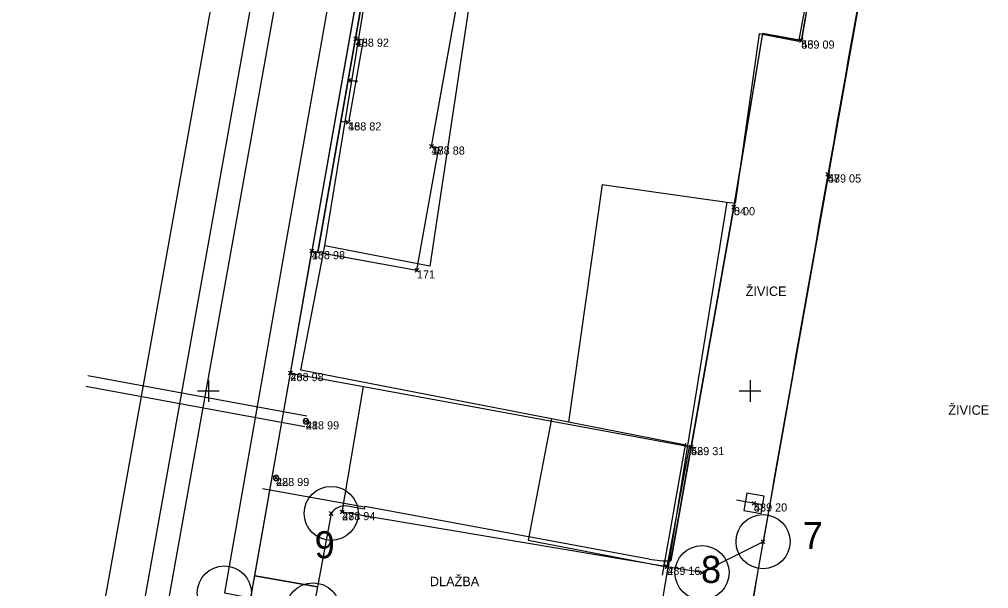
# Model space of a CAD drawing. Extents: x -866624 to -866276, y -1050208 to -1049940.
# Drawn here: x -866486.98 to -866451.2, y -1050047.29 to -1050026.29 of the extents above; entities that cross this region are included whole.
import ezdxf

# ---------------------------------------------------------------- set-up
doc = ezdxf.new("R2010")
doc.units = 0
for name, color, linetype in [('00_BODY VYTYČ', 7, 'Continuous'), ('00_POMOCNÉ KCE', 7, 'Continuous'), ('09_PODLAHY', 7, 'Continuous'), ('bod-cislo', 7, 'Continuous'), ('bod-oznac', 7, 'Continuous'), ('bod-vyska', 7, 'Continuous'), ('BUDOVY', 7, 'Continuous'), ('CTV-SIT', 7, 'Continuous'), ('Default', 7, 'Continuous'), ('EL-ZAR', 7, 'Continuous'), ('HRAN-LIN', 7, 'Continuous'), ('Hranice', 7, 'Continuous'), ('Hranice další', 7, 'Continuous'), ('Hranice-budov', 7, 'Continuous'), ('KOLEJ', 7, 'Continuous'), ('POTR-ZAR', 7, 'Continuous'), ('TEXT', 7, 'Continuous')]:
    doc.layers.add(name, color=color, linetype=linetype)

# ---------------------------------------------------------------- blocks, each defined once
blk = doc.blocks.new('POINT_DISPLAY')
at = {"layer": 'Default'}
for p, q in [((-0.071, 0.071), (0.071, -0.071)), ((0.071, 0.071), (-0.071, -0.071))]:
    blk.add_line(p, q, dxfattribs=at)
blk = doc.blocks.new('CTVSIT')
at = {"layer": 'Default'}
for p, q in [((0, 2), (0, -2)), ((-2, 0), (2, 0))]:
    blk.add_line(p, q, dxfattribs=at)
blk = doc.blocks.new('200SAH')
at = {"layer": 'POTR-ZAR'}
for p, q in [((0, -0.325), (0, 0.65)), ((0.325, 0.325), (-0.325, 0.325)), ((-0.325, 0.325), (-0.325, -0.325)), ((0.325, -0.325), (0.325, 0.325)), ((-0.325, -0.325), (0.325, -0.325))]:
    blk.add_line(p, q, dxfattribs=at)
blk = doc.blocks.new('vytyčení')
at = {"layer": '00_POMOCNÉ KCE'}
for centre in [(-866034.112, -1050068.345), (-866032.646, -1050070.404), (-866032.762, -1050084.264), (-866029.142, -1050084.394), (-866029.271, -1050087.726)]:
    blk.add_circle(centre, 0.998, dxfattribs=at)
for centre, radius, start, end in [((-865794.817, -1039948.575), 10122.593, 268.4556412, 268.567516), ((-865314.028, -1020722.218), 29354.96, 268.567516, 268.6067194)]:
    blk.add_arc(centre, radius, start, end, dxfattribs=at)
at = {"layer": '09_PODLAHY'}
for points in [[(-866081.414, -1050069.09), (-866081.361, -1050067.121), (-866034.112, -1050068.345), (-866032.646, -1050070.404), (-866032.668, -1050071.704), (-866032.671, -1050071.836), (-866032.872, -1050071.831), (-866032.905, -1050071.604), (-866037.17, -1050071.494), (-866046.156, -1050071.254), (-866052.647, -1050071.161), (-866052.609, -1050069.711), (-866064.905, -1050069.395), (-866064.942, -1050070.845), (-866070.764, -1050070.735), (-866070.738, -1050069.285), (-866080.614, -1050069.109), (-866081.414, -1050069.09)], [(-866037.659, -1050086.526), (-866037.57, -1050083.788), (-866037.437, -1050079.693), (-866037.181, -1050071.494), (-866032.905, -1050071.604)], [(-866037.285, -1050071.717), (-866032.335, -1050071.845)], [(-866032.847, -1050072.408), (-866033.195, -1050083.08), (-866033.095, -1050083.083), (-866033.115, -1050083.714)], [(-866033.176, -1050083.08), (-866033.275, -1050086.913)], [(-866032.762, -1050084.264), (-866030.008, -1050084.365), (-866030.067, -1050086.709), (-866037.659, -1050086.526)], [(-866037.659, -1050086.526), (-866042.227, -1050086.418), (-866042.221, -1050086.198), (-866057.536, -1050085.815), (-866068.352, -1050085.544), (-866071.502, -1050085.465), (-866076.384, -1050085.343), (-866076.386, -1050085.562), (-866042.227, -1050086.418)]]:
    blk.add_lwpolyline(points, dxfattribs=at)
for points in [[(-866042.22, -1050086.198), (-866042.104, -1050082.475), (-866046.696, -1050082.351), (-866046.704, -1050082.624), (-866057.447, -1050082.335), (-866057.533, -1050085.497), (-866057.536, -1050085.815), (-866042.22, -1050086.198)], [(-866030.068, -1050086.709), (-866030.008, -1050084.365), (-866029.142, -1050084.394), (-866029.234, -1050086.729), (-866030.068, -1050086.709)], [(-866076.389, -1050085.553), (-866077.898, -1050085.519), (-866077.927, -1050086.627), (-866076.412, -1050086.552), (-866042.25, -1050087.417), (-866029.271, -1050087.726), (-866029.245, -1050086.729)]]:
    blk.add_lwpolyline(points, close=True, dxfattribs=at)
for centre, radius, start, end in [((-866036.697, -1050072.283), 3.852, 358.1389, 10.1522), ((-866032.516, -1050083.718), 0.599, 179.6517, 245.7505)]:
    blk.add_arc(centre, radius, start, end, dxfattribs=at)

msp = doc.modelspace()

# ---------------------------------------------------------------- linework, layer by layer
at = {"layer": 'BUDOVY'}
for p, q in [((-866471.76, -1050030.98), (-866467.37, -1050006.42)), ((-866455.96, -1050014.96), (-866458.11, -1050027.07)), ((-866459.538, -1050026.817), (-866460.6, -1050033.22)), ((-866458.11, -1050027.07), (-866459.538, -1050026.817)), ((-866472.3, -1050035.55), (-866471.492, -1050031.028)), ((-866471.76, -1050030.98), (-866471.492, -1050031.028)), ((-866460.6, -1050033.22), (-866462.18, -1050042.07)), ((-866476.97, -1050039.34), (-866476.18, -1050034.84)), ((-866476.18, -1050034.84), (-866472.3, -1050035.55)), ((-866476.97, -1050039.34), (-866474.276, -1050039.837)), ((-866475.06, -1050044.47), (-866474.276, -1050039.837)), ((-866463.06, -1050046.49), (-866462.242, -1050042.059)), ((-866462.242, -1050042.059), (-866462.18, -1050042.07)), ((-866463.06, -1050046.49), (-866475.06, -1050044.47))]:
    msp.add_line(p, q, dxfattribs=at)
at = {"layer": 'EL-ZAR'}
for p, q in [((-866484.449, -1050039.431), (-866476.364, -1050040.923)), ((-866484.52, -1050039.825), (-866476.436, -1050041.317))]:
    msp.add_line(p, q, dxfattribs=at)
for centre, start, end in [((-866476.4, -1050041.12), 0, 180), ((-866476.4, -1050041.12), 180, 0), ((-866477.5, -1050043.21), 0, 180), ((-866477.5, -1050043.21), 180, 0)]:
    msp.add_arc(centre, 0.1, start, end, dxfattribs=at)
at = {"layer": 'HRAN-LIN'}
for p, q in [((-866472.79, -1049999.16), (-866484.714, -1050065.787)), ((-866475.964, -1050034.88), (-866470.013, -1050001.227)), ((-866474.813, -1050030.094), (-866474.275, -1050027.05)), ((-866474.57, -1050026.998), (-866474.275, -1050027.05)), ((-866474.839, -1050028.52), (-866474.7, -1050028.478)), ((-866474.839, -1050028.52), (-866474.544, -1050028.572)), ((-866474.839, -1050028.52), (-866474.723, -1050028.607)), ((-866475.108, -1050030.041), (-866474.813, -1050030.094)), ((-866459.523, -1050045.564), (-866461.778, -1050046.706)), ((-866461.778, -1050046.706), (-866463.06, -1050046.49))]:
    msp.add_line(p, q, dxfattribs=at)
msp.add_circle((-866474.544, -1050028.572), 0.0283, dxfattribs=at)
for centre, radius, start, end in [((-856489.119, -1051794.291), 10122.592, 169.8621961, 169.9740709), ((-837550.449, -1055142.527), 29354.959, 169.9740709, 170.0132744)]:
    msp.add_arc(centre, radius, start, end, dxfattribs=at)
at = {"layer": 'Hranice'}
for p, q in [((-866475.7, -1050034.65), (-866470.23, -1050001.19)), ((-866455.89, -1050014.99), (-866458.22, -1050027.11)), ((-866459.67, -1050026.83), (-866460.55, -1050033.07)), ((-866458.22, -1050027.11), (-866459.67, -1050026.83)), ((-866460.86, -1050033.03), (-866462.31, -1050042.01)), ((-866460.86, -1050033.03), (-866460.55, -1050033.07)), ((-866476.59, -1050039.23), (-866475.7, -1050034.65)), ((-866467.33, -1050041.03), (-866476.59, -1050039.23)), ((-866467.33, -1050041.03), (-866468.19, -1050045.51)), ((-866462.31, -1050042.01), (-866463.03, -1050046.5)), ((-866468.19, -1050045.51), (-866463.03, -1050046.5)), ((-866464.96, -1050058.01), (-866463.03, -1050046.5))]:
    msp.add_line(p, q, dxfattribs=at)
at = {"layer": 'Hranice další'}
for p, q in [((-866467.44, -1050006.35), (-866471.83, -1050035.4)), ((-866465.46, -1050032.38), (-866466.7, -1050041.15)), ((-866465.46, -1050032.38), (-866460.86, -1050033.03)), ((-866471.83, -1050035.4), (-866475.7, -1050034.65)), ((-866466.7, -1050041.15), (-866467.33, -1050041.03)), ((-866462.31, -1050042.01), (-866466.7, -1050041.15))]:
    msp.add_line(p, q, dxfattribs=at)
at = {"layer": 'Hranice-budov'}
for p, q in [((-866467.44, -1050006.35), (-866471.83, -1050035.4)), ((-866455.89, -1050014.99), (-866458.22, -1050027.11)), ((-866459.67, -1050026.83), (-866460.55, -1050033.07)), ((-866458.22, -1050027.11), (-866459.67, -1050026.83)), ((-866465.46, -1050032.38), (-866466.7, -1050041.15)), ((-866465.46, -1050032.38), (-866460.86, -1050033.03)), ((-866460.86, -1050033.03), (-866460.55, -1050033.07)), ((-866476.59, -1050039.23), (-866475.7, -1050034.65)), ((-866471.83, -1050035.4), (-866475.7, -1050034.65)), ((-866467.33, -1050041.03), (-866476.59, -1050039.23)), ((-866466.7, -1050041.15), (-866467.33, -1050041.03))]:
    msp.add_line(p, q, dxfattribs=at)
at = {"layer": 'KOLEJ'}
for p, q in [((-866473.069, -1049987.559), (-866486.976, -1050065.382)), ((-866471.656, -1049987.812), (-866485.563, -1050065.635))]:
    msp.add_line(p, q, dxfattribs=at)

# ---------------------------------------------------------------- block references
at = {"layer": '00_BODY VYTYČ'}
for p in [(-866475.464, -1050044.52), (-866459.523, -1050045.564), (-866461.778, -1050046.706)]:
    msp.add_blockref('POINT_DISPLAY', p, dxfattribs=at)
at = {"layer": '00_POMOCNÉ KCE', "rotation": -98.59344504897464}
msp.add_blockref('vytyčení', (42415.469, -2063260.675), dxfattribs=at)
at = {"layer": '00_POMOCNÉ KCE'}
for p in [(-866459.523, -1050045.564), (-866461.778, -1050046.706)]:
    msp.add_blockref('POINT_DISPLAY', p, dxfattribs=at)
at = {"layer": 'bod-oznac'}
for p in [(-866474.56, -1050027), (-866458.11, -1050027.07), (-866474.84, -1050030.09), (-866471.76, -1050030.98), (-866457.13, -1050032.01), (-866460.6, -1050033.22), (-866476.18, -1050034.84), (-866472.3, -1050035.55), (-866476.97, -1050039.34), (-866476.4, -1050041.12), (-866462.18, -1050042.07), (-866477.5, -1050043.21), (-866459.86, -1050044.15), (-866475.06, -1050044.47), (-866463.06, -1050046.49)]:
    msp.add_blockref('POINT_DISPLAY', p, dxfattribs=at)
at = {"layer": 'CTV-SIT', "xscale": 0.19999999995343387, "yscale": 0.19999999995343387}
for p in [(-866480, -1050040), (-866460, -1050040)]:
    msp.add_blockref('CTVSIT', p, dxfattribs=at)
at = {"layer": 'POTR-ZAR', "rotation": 79.99695713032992}
msp.add_blockref('200SAH', (-866459.86, -1050044.15), dxfattribs=at)

# ---------------------------------------------------------------- texts
at = {"layer": '00_BODY VYTYČ'}
for s, p in [('9', (-866476.077, -1050046.176)), ('7', (-866458.06, -1050045.833)), ('8', (-866461.815, -1050047.085))]:
    msp.add_text(s, height=1, dxfattribs=at).set_placement(p)
at = {"layer": 'bod-cislo'}
for s, p in [('15', (-866474.56, -1050027.3)), ('55', (-866458.11, -1050027.37)), ('16', (-866474.84, -1050030.39)), ('17', (-866471.76, -1050031.28)), ('57', (-866457.13, -1050032.31)), ('54', (-866460.6, -1050033.52)), ('18', (-866476.18, -1050035.14)), ('171', (-866472.3, -1050035.85)), ('20', (-866476.97, -1050039.64)), ('21', (-866476.4, -1050041.42)), ('52', (-866462.18, -1050042.37)), ('22', (-866477.5, -1050043.51)), ('53', (-866459.86, -1050044.45)), ('27', (-866475.06, -1050044.77)), ('28', (-866463.06, -1050046.79))]:
    msp.add_text(s, height=0.3, dxfattribs=at).set_placement(p)
at = {"layer": 'bod-vyska'}
for s, p in [('488 92', (-866474.56, -1050027.3)), ('489 09', (-866458.11, -1050027.37)), ('488 82', (-866474.84, -1050030.39)), ('488 88', (-866471.76, -1050031.28)), ('489 05', (-866457.13, -1050032.31)), ('0 00', (-866460.6, -1050033.52)), ('488 98', (-866476.18, -1050035.14)), ('488 98', (-866476.97, -1050039.64)), ('488 99', (-866476.4, -1050041.42)), ('489 31', (-866462.18, -1050042.37)), ('488 99', (-866477.5, -1050043.51)), ('489 20', (-866459.86, -1050044.45)), ('488 94', (-866475.06, -1050044.77)), ('489 16', (-866463.06, -1050046.79))]:
    msp.add_text(s, height=0.3, dxfattribs=at).set_placement(p)
at = {"layer": 'TEXT'}
for s, p in [('ŽIVICE', (-866460.165, -1050036.497)), ('ŽIVICE', (-866452.685, -1050040.88)), ('DLAŽBA', (-866471.822, -1050047.205))]:
    msp.add_text(s, height=0.35, dxfattribs=at).set_placement(p)

doc.saveas('drawing.dxf')
